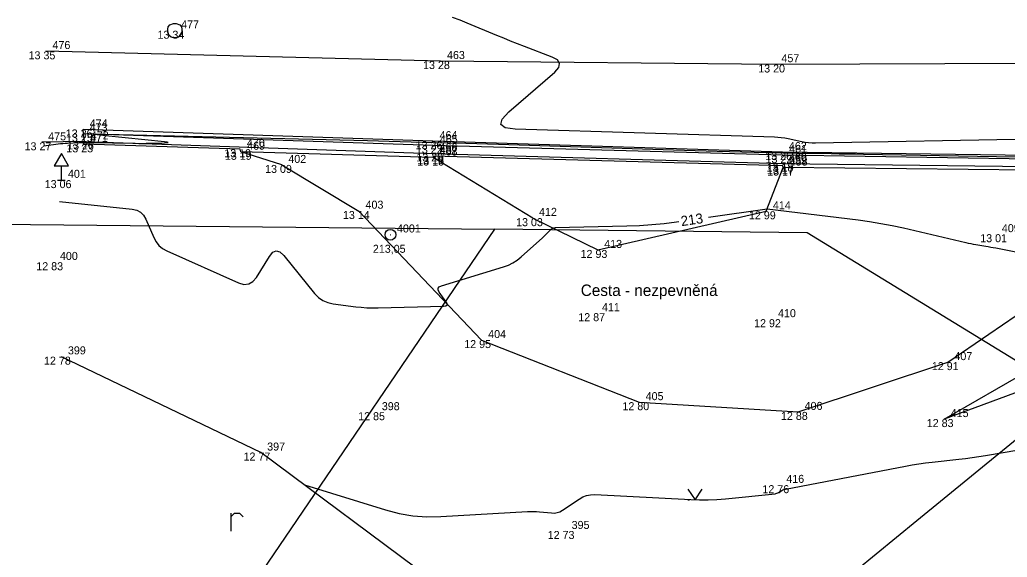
# Model space of a CAD drawing. Extents: x -703403 to -701924, y -1022520 to -1021856.
# Drawn here: x -703356.45 to -703321.9, y -1022198.84 to -1022180.06 of the extents above; entities that cross this region are included whole.
import ezdxf

# ---------------------------------------------------------------- set-up
doc = ezdxf.new("R2010")
doc.units = 0
for name, color, linetype in [('Ex_Contour Labels', 7, 'Continuous'), ('Ex_Major Contours', 7, 'Continuous'), ('Ex_Minor Contours', 7, 'Continuous'), ('Z_bodove_pole', 7, 'Continuous'), ('Z_bodove_pole_cisla', 7, 'Continuous'), ('Z_bodove_pole_vysky', 7, 'Continuous'), ('Z_body', 7, 'Continuous'), ('Z_body_cisla', 7, 'Continuous'), ('Z_body_vysky_redukovane', 7, 'Continuous'), ('Z_dopravni_znacky', 7, 'Continuous'), ('Z_hrany_paty', 7, 'Continuous'), ('Z_katastr_hranice', 7, 'Continuous'), ('Z_komunikace', 7, 'Continuous'), ('Z_komunikace_osa', 7, 'Continuous'), ('Z_obruba', 7, 'Continuous'), ('Z_pole_rozhranni', 7, 'Continuous'), ('Z_popisy', 7, 'Continuous'), ('Z_rozhranni', 7, 'Continuous'), ('Z_site_kanalizace_znaky', 7, 'Continuous'), ('Z_zlabek', 7, 'Continuous'), ('Z_znaky_kultur', 7, 'Continuous')]:
    doc.layers.add(name, color=color, linetype=linetype)

# ---------------------------------------------------------------- blocks, each defined once
blk = doc.blocks.new('POINT_DISPLAY')
blk.add_line((0, 0), (0, 0))
blk = doc.blocks.new('Z620')
for p, q in [((-0.25, 0.05), (-0.23, 0.13)), ((-0.25, -0.05), (-0.25, 0.05)), ((-0.23, 0.13), (-0.17, 0.2)), ((-0.17, 0.2), (-0.05, 0.25)), ((-0.05, 0.25), (0.05, 0.25)), ((0.05, 0.25), (0.17, 0.2)), ((0.17, 0.2), (0.23, 0.13)), ((0.23, 0.13), (0.25, 0.05)), ((0.25, 0.05), (0.25, -0.05)), ((-0.2, -0.17), (-0.25, -0.05)), ((-0.13, -0.23), (-0.2, -0.17)), ((-0.05, -0.25), (-0.13, -0.23)), ((0.05, -0.25), (-0.05, -0.25)), ((0.13, -0.23), (0.05, -0.25)), ((0.2, -0.17), (0.13, -0.23)), ((0.25, -0.05), (0.2, -0.17))]:
    blk.add_line(p, q)
blk = doc.blocks.new('Z527')
for p, q in [((0, 0.93), (-0.25, 0.5)), ((0.25, 0.5), (0, 0.93)), ((-0.25, 0.5), (0.25, 0.5)), ((0, 0), (0, 0.5)), ((-0.13, 0), (0.13, 0))]:
    blk.add_line(p, q)
blk = doc.blocks.new('Z314')
for p, q in [((-0.25, 0.17), (0, -0.2)), ((0, -0.2), (0.25, 0.17)), ((-0.25, -0.2), (-0.2, -0.2)), ((0.2, -0.2), (0.25, -0.2))]:
    blk.add_line(p, q)
blk = doc.blocks.new('Z301')
for p, q in [((-0.13, 0.38), (-0.13, -0.25)), ((-0.13, 0.25), (0, 0.38)), ((0, 0.38), (0.17, 0.38)), ((0.17, 0.38), (0.3, 0.25))]:
    blk.add_line(p, q)
blk = doc.blocks.new('Z101')
for radius in [0.188, 0.0025]:
    blk.add_circle((0, 0), radius)

msp = doc.modelspace()

# ---------------------------------------------------------------- linework, layer by layer
at = {"layer": 'Ex_Major Contours'}
for points in [[(-703355.06, -1022186.409), (-703352.513, -1022186.671), (-703352.353, -1022186.707), (-703352.219, -1022186.778), (-703352.112, -1022186.885), (-703352.03, -1022187.027), (-703351.757, -1022187.668), (-703351.677, -1022187.817), (-703351.575, -1022187.943), (-703351.45, -1022188.048), (-703351.302, -1022188.13), (-703348.788, -1022189.249), (-703348.601, -1022189.303), (-703348.435, -1022189.289), (-703348.29, -1022189.207), (-703348.166, -1022189.058), (-703347.712, -1022188.324), (-703347.596, -1022188.184), (-703347.474, -1022188.132), (-703347.346, -1022188.168), (-703347.213, -1022188.291), (-703346.129, -1022189.625), (-703345.994, -1022189.763), (-703345.842, -1022189.869), (-703345.672, -1022189.942), (-703345.483, -1022189.984), (-703344.694, -1022190.084), (-703344.497, -1022190.105), (-703344.299, -1022190.119), (-703344.101, -1022190.125), (-703343.902, -1022190.124), (-703341.619, -1022190.068), (-703341.539, -1022190.056), (-703341.498, -1022190.024), (-703341.497, -1022189.972), (-703341.535, -1022189.9), (-703341.768, -1022189.573), (-703341.807, -1022189.498), (-703341.808, -1022189.436), (-703341.77, -1022189.387), (-703341.693, -1022189.352), (-703339.52, -1022188.693), (-703339.351, -1022188.632), (-703339.191, -1022188.553), (-703339.041, -1022188.457), (-703338.9, -1022188.344), (-703338.161, -1022187.679), (-703338.125, -1022187.645), (-703338.089, -1022187.611), (-703338.054, -1022187.576), (-703338.02, -1022187.54), (-703337.884, -1022187.395), (-703337.848, -1022187.364), (-703337.808, -1022187.341), (-703337.764, -1022187.326), (-703337.717, -1022187.321), (-703335.204, -1022187.263), (-703334.769, -1022187.246), (-703334.335, -1022187.217), (-703333.902, -1022187.174), (-703333.471, -1022187.118), (-703333.392, -1022187.107)], [(-703332.353, -1022186.958), (-703330.299, -1022186.662), (-703330.298, -1022186.663), (-703330.296, -1022186.665), (-703327.12, -1022187.052), (-703326.721, -1022187.107), (-703326.324, -1022187.171), (-703325.929, -1022187.247), (-703325.535, -1022187.333), (-703323.355, -1022187.84), (-703323.268, -1022187.859), (-703323.181, -1022187.877), (-703323.093, -1022187.894), (-703323.005, -1022187.909), (-703322.653, -1022187.968), (-703322.565, -1022187.983), (-703322.477, -1022187.998), (-703322.389, -1022188.014), (-703322.302, -1022188.031), (-703319.25, -1022188.629)]]:
    msp.add_lwpolyline(points, dxfattribs=at)
at = {"layer": 'Ex_Minor Contours'}
for points in [[(-703320.999, -1022184.23), (-703328.61, -1022184.367), (-703328.731, -1022184.365), (-703328.852, -1022184.357), (-703328.972, -1022184.342), (-703329.091, -1022184.321), (-703329.567, -1022184.22), (-703329.686, -1022184.198), (-703329.806, -1022184.181), (-703329.927, -1022184.169), (-703330.048, -1022184.162), (-703339.118, -1022183.881), (-703339.461, -1022183.833), (-703339.611, -1022183.716), (-703339.568, -1022183.53), (-703339.333, -1022183.276), (-703337.733, -1022181.884), (-703337.592, -1022181.724), (-703337.561, -1022181.584), (-703337.639, -1022181.462), (-703337.826, -1022181.36), (-703338.792, -1022180.99), (-703339.033, -1022180.897), (-703339.273, -1022180.802), (-703339.513, -1022180.705), (-703339.752, -1022180.606), (-703340.79, -1022180.171), (-703341.044, -1022180.071), (-703341.302, -1022179.98)], [(-703355.605, -1022184.466), (-703355.106, -1022184.398), (-703355.023, -1022184.387), (-703354.94, -1022184.379), (-703354.856, -1022184.372), (-703354.772, -1022184.368), (-703354.378, -1022184.351), (-703354.284, -1022184.348), (-703354.19, -1022184.346), (-703354.096, -1022184.345), (-703354.002, -1022184.345), (-703353.599, -1022184.347), (-703353.5, -1022184.348), (-703353.401, -1022184.349), (-703353.303, -1022184.351), (-703353.204, -1022184.354), (-703352.403, -1022184.374), (-703352.276, -1022184.376), (-703352.148, -1022184.376), (-703352.021, -1022184.375), (-703351.894, -1022184.371), (-703351.385, -1022184.354), (-703351.289, -1022184.348), (-703351.257, -1022184.341), (-703351.289, -1022184.331), (-703351.384, -1022184.32), (-703353.448, -1022184.116), (-703353.737, -1022184.084), (-703353.833, -1022184.064), (-703353.735, -1022184.055), (-703353.444, -1022184.059), (-703344.281, -1022184.282), (-703343.134, -1022184.311), (-703341.988, -1022184.341), (-703340.841, -1022184.374), (-703339.694, -1022184.409), (-703333.579, -1022184.599), (-703333.197, -1022184.61), (-703332.815, -1022184.622), (-703332.433, -1022184.633), (-703332.051, -1022184.644), (-703330.324, -1022184.692), (-703330.041, -1022184.699), (-703329.757, -1022184.706), (-703329.474, -1022184.711), (-703329.191, -1022184.716), (-703328.059, -1022184.734), (-703327.776, -1022184.738), (-703327.493, -1022184.743), (-703327.209, -1022184.747), (-703326.926, -1022184.752), (-703321.614, -1022184.842)], [(-703346.49, -1022196.31), (-703343.652, -1022197.185), (-703343.177, -1022197.309), (-703342.696, -1022197.389), (-703342.21, -1022197.425), (-703341.718, -1022197.418), (-703338.686, -1022197.241), (-703338.58, -1022197.237), (-703338.475, -1022197.237), (-703338.37, -1022197.241), (-703338.265, -1022197.25), (-703337.845, -1022197.292), (-703337.743, -1022197.294), (-703337.644, -1022197.279), (-703337.55, -1022197.246), (-703337.461, -1022197.196), (-703336.881, -1022196.804), (-703336.752, -1022196.731), (-703336.617, -1022196.681), (-703336.475, -1022196.654), (-703336.327, -1022196.65), (-703332.967, -1022196.822), (-703332.666, -1022196.832), (-703332.364, -1022196.831), (-703332.063, -1022196.818), (-703331.761, -1022196.793), (-703330.024, -1022196.619), (-703329.991, -1022196.614), (-703329.958, -1022196.605), (-703329.927, -1022196.592), (-703329.898, -1022196.576), (-703329.781, -1022196.503), (-703329.751, -1022196.486), (-703329.72, -1022196.472), (-703329.688, -1022196.462), (-703329.655, -1022196.454), (-703325.462, -1022195.651), (-703325.23, -1022195.609), (-703324.997, -1022195.572), (-703324.764, -1022195.54), (-703324.53, -1022195.513), (-703323.592, -1022195.415), (-703323.358, -1022195.388), (-703323.124, -1022195.358), (-703322.891, -1022195.324), (-703322.659, -1022195.286), (-703319.777, -1022194.79)]]:
    msp.add_lwpolyline(points, dxfattribs=at)
at = {"layer": 'Z_hrany_paty'}
for p, q in [((-703324.11, -1022194.01), (-703317.7, -1022190.33)), ((-703319.26, -1022192.23), (-703324.11, -1022194.01))]:
    msp.add_line(p, q, dxfattribs=at)
at = {"layer": 'Z_katastr_hranice'}
for p, q in [((-703398.807, -1022186.75), (-703339.84, -1022187.38)), ((-703339.84, -1022187.38), (-703351.88, -1022205.07)), ((-703328.9, -1022187.5), (-703339.84, -1022187.38)), ((-703319.68, -1022193.15), (-703328.9, -1022187.5)), ((-703325.07, -1022197.56), (-703319.68, -1022193.15)), ((-703327.2, -1022199.3), (-703325.07, -1022197.56))]:
    msp.add_line(p, q, dxfattribs=at)
at = {"layer": 'Z_komunikace'}
for p, q in [((-703341.99, -1022184.3), (-703354.23, -1022183.89)), ((-703354.22, -1022184.04), (-703354.23, -1022183.89)), ((-703354.18, -1022184.31), (-703355.67, -1022184.34)), ((-703354.18, -1022184.31), (-703354.22, -1022184.04)), ((-703329.76, -1022184.68), (-703341.99, -1022184.3)), ((-703320.67, -1022184.81), (-703329.76, -1022184.68))]:
    msp.add_line(p, q, dxfattribs=at)
at = {"layer": 'Z_komunikace_osa'}
for p, q in [((-703341.73, -1022181.5), (-703355.53, -1022181.16)), ((-703330.03, -1022181.62), (-703341.73, -1022181.5)), ((-703320.69, -1022181.59), (-703330.03, -1022181.62))]:
    msp.add_line(p, q, dxfattribs=at)
at = {"layer": 'Z_obruba'}
for p, q in [((-703341.98, -1022184.45), (-703354.22, -1022184.04)), ((-703354.21, -1022184.41), (-703354.18, -1022184.31)), ((-703348.73, -1022184.58), (-703354.21, -1022184.41)), ((-703348.71, -1022184.67), (-703348.73, -1022184.58)), ((-703329.75, -1022184.79), (-703341.98, -1022184.45)), ((-703341.98, -1022184.87), (-703348.71, -1022184.67)), ((-703329.75, -1022185.16), (-703341.98, -1022184.82)), ((-703341.98, -1022184.82), (-703341.98, -1022184.87)), ((-703320.69, -1022184.93), (-703329.75, -1022184.79)), ((-703329.74, -1022185.22), (-703329.75, -1022185.16)), ((-703320.71, -1022185.32), (-703329.74, -1022185.22))]:
    msp.add_line(p, q, dxfattribs=at)
at = {"layer": 'Z_pole_rozhranni'}
for p, q in [((-703348.01, -1022195.18), (-703354.99, -1022191.83)), ((-703341.93, -1022199.7), (-703348.01, -1022195.18))]:
    msp.add_line(p, q, dxfattribs=at)
at = {"layer": 'Z_rozhranni'}
for p, q in [((-703347.28, -1022185.13), (-703348.71, -1022184.67)), ((-703338.5, -1022186.99), (-703341.98, -1022184.87)), ((-703347.28, -1022185.13), (-703344.58, -1022186.74)), ((-703330.33, -1022186.75), (-703329.74, -1022185.22)), ((-703344.58, -1022186.74), (-703340.29, -1022191.25)), ((-703338.5, -1022186.99), (-703336.22, -1022188.1)), ((-703336.22, -1022188.1), (-703330.33, -1022186.75)), ((-703323.98, -1022192.02), (-703318.53, -1022188.29)), ((-703340.29, -1022191.25), (-703334.78, -1022193.42)), ((-703329.21, -1022193.76), (-703323.98, -1022192.02)), ((-703334.78, -1022193.42), (-703329.21, -1022193.76))]:
    msp.add_line(p, q, dxfattribs=at)
at = {"layer": 'Z_zlabek'}
for p, q in [((-703354.18, -1022184.31), (-703341.99, -1022184.73)), ((-703341.99, -1022184.73), (-703329.76, -1022185.08)), ((-703329.76, -1022185.08), (-703320.67, -1022185.19))]:
    msp.add_line(p, q, dxfattribs=at)

# ---------------------------------------------------------------- block references
at = {"layer": 'Z_bodove_pole'}
msp.add_blockref('Z101', (-703343.48, -1022187.57), dxfattribs=at)
at = {"layer": 'Z_body'}
for p in [(-703351.02, -1022180.44), (-703355.53, -1022181.16), (-703341.73, -1022181.5), (-703330.03, -1022181.62), (-703354.23, -1022183.89), (-703354.22, -1022184.04), (-703354.18, -1022184.31), (-703341.99, -1022184.3), (-703355.67, -1022184.34), (-703354.21, -1022184.41), (-703348.73, -1022184.58), (-703341.98, -1022184.45), (-703348.71, -1022184.67), (-703341.99, -1022184.73), (-703341.98, -1022184.82), (-703341.98, -1022184.87), (-703329.76, -1022184.68), (-703329.75, -1022184.79), (-703347.28, -1022185.13), (-703329.76, -1022185.08), (-703329.75, -1022185.16), (-703329.74, -1022185.22), (-703354.99, -1022185.66), (-703344.58, -1022186.74), (-703338.5, -1022186.99), (-703330.33, -1022186.75), (-703343.48, -1022187.57), (-703322.31, -1022187.55), (-703336.22, -1022188.1), (-703355.26, -1022188.53), (-703336.3, -1022190.31), (-703330.15, -1022190.52), (-703340.29, -1022191.25), (-703354.99, -1022191.83), (-703323.98, -1022192.02), (-703334.78, -1022193.42), (-703344, -1022193.77), (-703329.21, -1022193.76), (-703324.11, -1022194.01), (-703348.01, -1022195.18), (-703329.86, -1022196.32), (-703337.37, -1022197.92)]:
    msp.add_blockref('POINT_DISPLAY', p, dxfattribs=at)
at = {"layer": 'Z_dopravni_znacky'}
msp.add_blockref('Z527', (-703354.99, -1022185.66), dxfattribs=at)
at = {"layer": 'Z_site_kanalizace_znaky'}
msp.add_blockref('Z620', (-703351.02, -1022180.44), dxfattribs=at)
at = {"layer": 'Z_znaky_kultur'}
for name, p in [('Z314', (-703332.82, -1022196.63)), ('Z301', (-703348.93, -1022197.68))]:
    msp.add_blockref(name, p, dxfattribs=at)

# ---------------------------------------------------------------- texts
at = {"layer": 'Ex_Contour Labels'}
msp.add_text('213', height=0.35, rotation=8.1911, dxfattribs=at).set_placement((-703333.295, -1022187.27))
at = {"layer": 'Z_bodove_pole_cisla'}
msp.add_text('4001', height=0.28, dxfattribs=at).set_placement((-703343.25, -1022187.49))
at = {"layer": 'Z_bodove_pole_vysky'}
msp.add_text('213,05', height=0.28, dxfattribs=at).set_placement((-703344.093, -1022188.2))
at = {"layer": 'Z_body_cisla'}
for s, p in [('477', (-703350.8, -1022180.36)), ('476', (-703355.3, -1022181.08)), ('463', (-703341.5, -1022181.43)), ('457', (-703329.8, -1022181.54)), ('474', (-703354, -1022183.82)), ('473', (-703354, -1022183.96)), ('472', (-703353.96, -1022184.24)), ('464', (-703341.76, -1022184.23)), ('475', (-703355.45, -1022184.27)), ('471', (-703353.99, -1022184.33)), ('470', (-703348.5, -1022184.5)), ('469', (-703348.49, -1022184.6)), ('465', (-703341.75, -1022184.37)), ('466', (-703341.76, -1022184.65)), ('468', (-703341.76, -1022184.8)), ('467', (-703341.75, -1022184.74)), ('462', (-703329.54, -1022184.61)), ('461', (-703329.53, -1022184.71)), ('402', (-703347.05, -1022185.06)), ('460', (-703329.54, -1022185)), ('459', (-703329.53, -1022185.08)), ('458', (-703329.51, -1022185.15)), ('401', (-703354.76, -1022185.58)), ('403', (-703344.35, -1022186.66)), ('412', (-703338.28, -1022186.91)), ('414', (-703330.1, -1022186.68)), ('409', (-703322.09, -1022187.48)), ('413', (-703336, -1022188.03)), ('400', (-703355.04, -1022188.45)), ('411', (-703336.08, -1022190.24)), ('410', (-703329.92, -1022190.45)), ('404', (-703340.06, -1022191.18)), ('399', (-703354.76, -1022191.75)), ('407', (-703323.75, -1022191.95)), ('405', (-703334.55, -1022193.35)), ('398', (-703343.78, -1022193.7)), ('406', (-703328.99, -1022193.69)), ('415', (-703323.88, -1022193.94)), ('397', (-703347.79, -1022195.11)), ('416', (-703329.63, -1022196.24)), ('395', (-703337.14, -1022197.85))]:
    msp.add_text(s, height=0.28, dxfattribs=at).set_placement(p)
at = {"layer": 'Z_body_vysky_redukovane'}
for s, p in [('13 34', (-703351.627, -1022180.72)), ('13 35', (-703356.137, -1022181.44)), ('13 28', (-703342.337, -1022181.78)), ('13 20', (-703330.613, -1022181.9)), ('13 26', (-703354.837, -1022184.17)), ('13 25', (-703354.827, -1022184.32)), ('13 26', (-703354.787, -1022184.59)), ('13 26', (-703342.597, -1022184.58)), ('13 27', (-703356.277, -1022184.62)), ('13 23', (-703354.817, -1022184.69)), ('13 19', (-703349.29, -1022184.86)), ('13 19', (-703349.27, -1022184.95)), ('13 22', (-703342.587, -1022184.73)), ('13 20', (-703342.573, -1022185.01)), ('13 18', (-703342.54, -1022185.1)), ('13 18', (-703342.54, -1022185.15)), ('13 26', (-703330.367, -1022184.96)), ('13 22', (-703330.357, -1022185.07)), ('13 09', (-703347.863, -1022185.41)), ('13 18', (-703330.32, -1022185.36)), ('13 17', (-703330.31, -1022185.44)), ('13 17', (-703330.3, -1022185.5)), ('13 06', (-703355.573, -1022185.94)), ('13 14', (-703345.14, -1022187.02)), ('13 03', (-703339.083, -1022187.27)), ('12 99', (-703330.937, -1022187.03)), ('13 01', (-703322.847, -1022187.83)), ('12 93', (-703336.827, -1022188.38)), ('12 83', (-703355.867, -1022188.81)), ('12 87', (-703336.907, -1022190.59)), ('12 92', (-703330.757, -1022190.8)), ('12 95', (-703340.897, -1022191.53)), ('12 78', (-703355.597, -1022192.11)), ('12 91', (-703324.54, -1022192.3)), ('12 80', (-703335.363, -1022193.7)), ('12 85', (-703344.607, -1022194.05)), ('12 88', (-703329.817, -1022194.04)), ('12 83', (-703324.717, -1022194.29)), ('12 77', (-703348.617, -1022195.46)), ('12 76', (-703330.467, -1022196.6)), ('12 73', (-703337.977, -1022198.2))]:
    msp.add_text(s, height=0.28, dxfattribs=at).set_placement(p)
at = {"layer": 'Z_popisy'}
msp.add_text('Cesta - nezpevněná', height=0.4, dxfattribs=at).set_placement((-703336.82, -1022189.71))

doc.saveas('drawing.dxf')
